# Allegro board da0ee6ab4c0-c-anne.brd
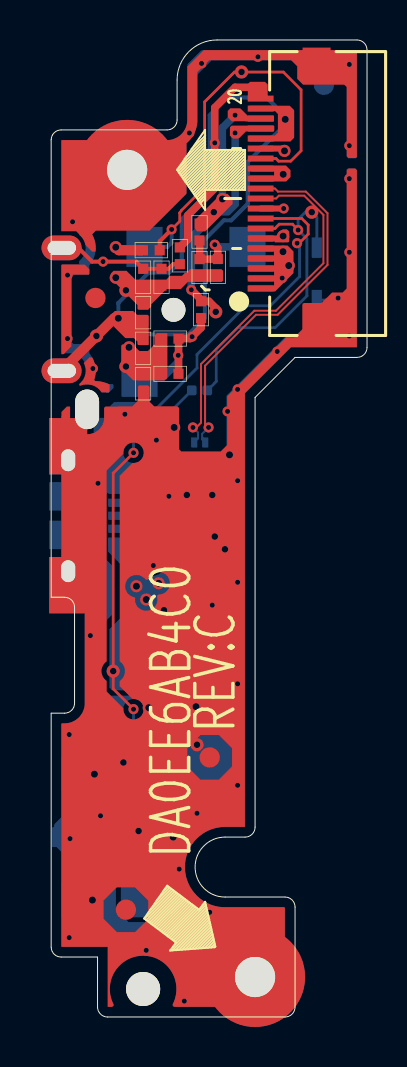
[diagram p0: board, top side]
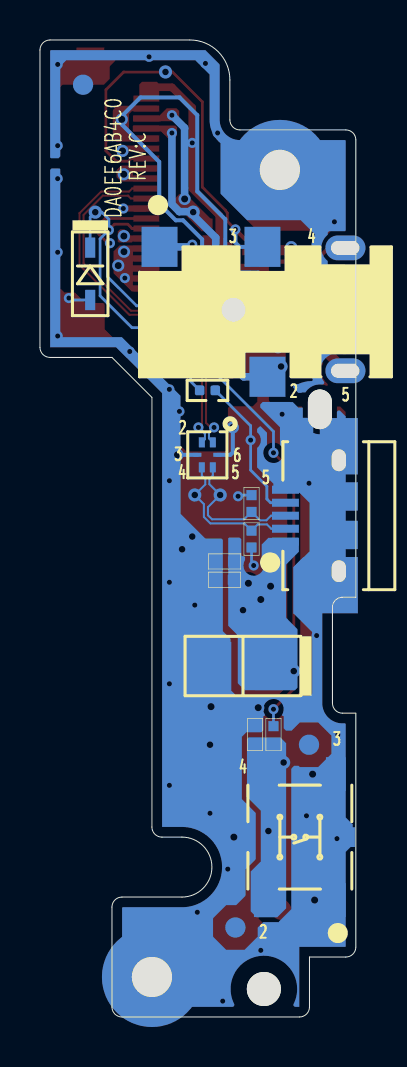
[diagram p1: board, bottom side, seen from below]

Outline 15.8 x 48.88 mm; copper layers: TOP, SGND, SVCC, BOTTOM. Coordinates in mm from the lower left corner of the outline.
Outline path: 0,43.88 arc(0.15,44.24) 0.5,44.38 5.8,44.38 arc(6.15,44.53) 6.3,44.88 6.3,46.88 arc(6.89,48.3) 8.3,48.88 15.3,48.88 arc(15.65,48.74) 15.8,48.38 15.8,33.5 arc(15.65,33.15) 15.3,33 12.2,33 10.2,31 10.2,9.5 arc(10.05,9.15) 9.7,9 8.7,9 arc(7.2,7.5) 8.7,6 11.7,6 arc(12.05,5.85) 12.2,5.5 12.2,0.5 arc(12.05,0.15) 11.7,0 2.82,0 arc(2.47,0.15) 2.32,0.5 2.32,3 0.5,3 arc(0.15,3.15) 0,3.5 0,15.2 0.67,15.2 arc(1.02,15.35) 1.17,15.7 1.17,20.5 arc(1.02,20.85) 0.67,21 0,21 0,32.01 0.89,32.01 arc(1.22,32.33) 0.89,32.66 0,32.66 0,38.15 0.89,38.15 arc(1.22,38.48) 0.89,38.8 0,38.8 0,43.88

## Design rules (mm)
constraint set DEFAULT: min track width 0.14
net group DFP-S4W4-TB: nets USB_FS_DM_R USB_FS_DP_R USBP4+_CN USBP4-_CN
net group W15-TB: nets HEADSET_MIC HP_OUT_L HP_OUT_L_CON HP_OUT_R HP_OUT_R_CON
net group W80-TB: nets DCIN_5V_IN

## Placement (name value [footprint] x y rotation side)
C1  330p/50v_4  [CC0402_S]  8.34 37.5 270 top
C2  330p/50v_4  [CC0402_S]  5.95 32.18 180 top
C3  330p/50v_4  [CC0402_S]  4.6 37.01 270 top
C4  470p/50v_4  [CC0402_S]  6.56 22.79 180 bottom
C5  0.1u/10v_4  [CC0402_S]  6.57 21.87 180 bottom
C6  150u/6.3v_3528  [CC3528]  5.64 17.56 180 bottom
CN1  88511-2001-20p-l  [88511-2001-20P-L]  13.78 41.2 90 top
CN2  2sj2342-000111f  [PHJK-2SJ2342-000111F-5P]  4.52 35.38 270 bottom
CN3  micro_usb2.0  [USB-2UB1000-000201F-5P-L]  0.85 25.08 90 bottom
D1  *5v/0.2p_4  [CC0402_S]  5.22 23.91 270 bottom
D2  *5v/0.2p_4  [CC0402_S]  5.22 25.69 90 bottom
D6  udzvte-173.3b  [DSM]  13.29 37.19 270 bottom
HOLE1  *h-c197d79p2  [H-C197D79P2]  10.2 2 0 top
HOLE2  *h-c197d79p2  [H-C197D79P2]  3.8 42.38 0 top
HOLE3  *h-c67d67n  [H-C67D67N]  4.6 1.4 0 top
HOLE4  *h-o47x78d47x78n  [H-O47X78D47X78N]  1.8 30.4 0 top
L3  33_4  [RC0402_S]  7.5 35.39 270 top
L4  33_4  [RC0402_S]  7.42 39.28 270 top
NOREF  -  []  7.43 -22.93 0 top
NOREF#2  -  [unnamed#2]  2.21 35.97 0 top
NOREF#3  -  []  -42.86 -64.59 0 top
NOREF#4  -  [unnamed#2]  7.93 12.99 0 top
NOREF#5  -  [unnamed#2]  3.74 5.37 0 top
NOREF#6  -  [unnamed#2]  6.02 4.48 180 bottom
NOREF#7  -  [unnamed#2]  13.64 46.64 180 bottom
NOREF#8  -  [unnamed#2]  2.34 13.62 180 bottom
R1  0_4  [RC0402_S]  6.44 38.08 270 top
R4  0_4  [RC0402_S]  4.6 33.46 90 top
R5  0_4  [RC0402_S]  4.6 31.68 90 top
R99  100/f_4  [RC0402]  7.42 31.35 180 bottom
R327  0_4  [RC0402_S]  4.12 14.13 270 bottom
SW1  tme-532w-q-t/r(439)  [SW-TC901-AA1G-A160T-6P]  2.8 9 0 bottom
T1  rclamp0531t  [RC0402_S]  7.42 37.5 90 top
T2  rclamp0531t  [RC0402_S]  5.95 33.94 0 top
T3  rclamp0531t  [RC0402_S]  5.52 37.01 90 top
T4  rclamp0531t  [RC0402_S]  4.6 35.23 270 top
T5  rclamp0531t  [RC0402_S]  5.01 38.36 0 top
T6  0.2pf/12v_4  [RC0402_S]  5.04 14.13 90 bottom
U3025  lxes11daa2-135  [FILTER-LXES11DAA2-135-6P]  7.43 28.12 180 bottom

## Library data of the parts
C1-C5 D1 D2 = CC0402_S
C6 = CC3528
CN1 = 88511-2001-20P-L
CN2 = PHJK-2SJ2342-000111F-5P
CN3 = USB-2UB1000-000201F-5P-L
D6 = DSM
HOLE1 HOLE2 = H-C197D79P2
HOLE3 = H-C67D67N
HOLE4 = H-O47X78D47X78N
L3 L4 R1 R4 R5 R327 T1-T6 = RC0402_S
R99 = RC0402
SW1 = SW-TC901-AA1G-A160T-6P
U3025 = FILTER-LXES11DAA2-135-6P

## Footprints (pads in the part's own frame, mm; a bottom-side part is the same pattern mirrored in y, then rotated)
88511-2001-20P-L
  rect 0.305x1.295 smd: 1(-4.75,3.3) 2(-4.25,3.3) 3(-3.75,3.3) 4(-3.25,3.3) 5(-2.75,3.3) 6(-2.25,3.3) 7(-1.75,3.3) 8(-1.25,3.3) 9(-0.75,3.3) 10(-0.25,3.3) 11(0.25,3.3) 12(0.75,3.3) 13(1.25,3.3) 14(1.75,3.3) 15(2.25,3.3) 16(2.75,3.3) 17(3.25,3.3) 18(3.75,3.3) 19(4.25,3.3) 20(4.75,3.3)
  rect 1.803x1.397 smd: 21(-6.4,0.5) 22(6.4,0.5)
CC0402_S
  rect 0.508x0.508 smd: 1(-0.42,0) 2(0.42,0)
CC3528
  rect 2.032x2.413 smd: 1(1.6,0) 2(-1.6,0)
DSM
  rect 1.016x0.508 smd: 1(-1.3,0) 2(1.321,0)
FILTER-LXES11DAA2-135-6P
  rect 0.305x0.508 smd: 1(0.275,0.625) 2(-0.275,0.625) 4(-0.275,-0.625) 5(0.275,-0.625)
  rect 0.406x0.203 smd: 3(-0.5,0) 6(0.5,0)
H-C67D67N
  round 1.702 hole 1.702 unplated: (0,0)
H-C197D79P2
  round 5.004 hole 2.007: 1(0,0)
H-O47X78D47X78N
  oval 1.194x1.981 hole 1.194x1.981 unplated: (0,0)
PHJK-2SJ2342-000111F-5P
  round 1.194 hole 1.194 unplated: (0,-1.6)
  rect 2.007x1.803 smd: 1(-3.15,-5.3) 2(3.35,0.1) 3(-3.15,-0.15)
  oval 1.245x2.007 hole 0.66x1.397: 4(-3.1,4) 5(3.05,4)
RC0402
  custom 0.12x0.12 smd: 1(0.39,0) 2(-0.39,0)
RC0402_S
  rect 0.508x0.508 smd: 1(-0.42,0) 2(0.42,0)
SW-TC901-AA1G-A160T-6P
  rect 0.991x1.702 smd: 1(-1.8,3.15) 2(1.8,3.15) 3(-1.8,-3.15) 4(1.8,-3.15)
  rect 0.457x0.991 smd: 5(-2.525,0) 6(2.525,0)
unnamed#2
  round 1.016 smd: 1(0,0)
USB-2UB1000-000201F-5P-L
  rect 0.406x1.346 smd: 1(-1.3,2.67) 2(-0.65,2.67) 3(0,2.67) 4(0.65,2.67) 5(1.3,2.67)
  rect 2.819x1.905 hole 1.092x0.711: 6(-2.775,0) 7(2.775,0)
  custom 0.25x0.25 smd: 8(-3.487,1.78) 9(3.487,1.78)
  rect 1.422x1.905 smd: 10(-0.962,0) 11(0.962,0)

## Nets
AGND: C1.2 C2.2 C3.2 CN1.15 CN1.22 HOLE2.1 R4.1 R5.2 T1.1 T2.1 T3.1 T4.1 T5.1
GND: C4.1 C5.1 C6.2 CN1.6 CN1.9 CN1.12 CN1.13 CN1.21 CN3.5 CN3.6 CN3.7 CN3.8 CN3.9 CN3.10 CN3.11 D1.2 D2.2 D6.2 HOLE1.1 R5.1 SW1.1 SW1.3 SW1.5 SW1.6 T6.2 U3025.3 U3025.6
COM_MIC_JACK: C3.1 CN2.4 R1.2 T3.2
DCIN_5V_IN: C4.2 C5.2 C6.1 CN1.1 CN1.2 CN1.3 CN1.4 CN1.5 CN3.1
HEADSET_MIC: CN1.20 R1.1
HOME_SCREEN: CN1.8 R327.1
HP_AGND: CN1.16 CN1.19 CN2.5 R4.2 T4.2
HP_DET: CN1.14 CN2.3 T5.2
HP_OUT_L: CN1.18 L4.1
HP_OUT_L_CON: C1.1 CN2.1 L4.2 T1.2
HP_OUT_R: CN1.17 L3.1
HP_OUT_R_CON: C2.1 CN2.2 L3.2 T2.2
USB_DCIN_IDN: CN1.7 D6.1 R99.2
USB_DCIN_IDN_C: CN3.4 R99.1
USB_FS_DM_R: CN1.11 U3025.2
USB_FS_DP_R: CN1.10 U3025.1
USBP4+_CN: CN3.3 D2.1 U3025.5
USBP4-_CN: CN3.2 D1.1 U3025.4
N38170283: R327.2 SW1.2 SW1.4 T6.1

Pads without a net: NOREF#2 1; NOREF#4 1; NOREF#5 1; NOREF#6 1; NOREF#7 1; NOREF#8 1

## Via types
v1: diameter 0.508, hole 0.254, TOP to BOTTOM, 53 vias
v2: diameter 0.66, hole 0.33, TOP to BOTTOM, 16 vias
v3: diameter 0.61, hole 0.356, TOP to BOTTOM, 21 vias

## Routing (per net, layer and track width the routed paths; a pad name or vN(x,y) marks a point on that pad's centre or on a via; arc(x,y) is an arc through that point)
AGND: length 2.7
  TOP w0.305: v3(11.67,43.33) 11.55,43.45 CN1.15
  TOP w0.508: T5.1 3.38,38.36 v3(3.23,38.51)
  vias: v1(0.82,37.12) v1(0.82,33.94) v1(1.07,39.78) v1(2.09,32.44) v1(6.91,44.23) v1(7.52,47.71) v1(10.34,48.04) v1(14.91,47.66) v1(14.91,43.59) v2(3.74,36.36) v2(3.74,32.55) v3(3.23,36.99) v3(3.89,33.5)
GND: length 9.8
  TOP w0.305: v1(11.63,40.45) 11.63,40.45 CN1.9
  BOTTOM w0.14: v1(5.89,26.05) 5.83,26.11 D2.2 ; v1(14.35,35.97) 14.26,35.87 D6.2 ; v1(5.11,22.59) 5.22,22.69 D1.2
  BOTTOM w0.203: v3(6.15,29.5) 6.15,28.25 6.28,28.12 U3025.6 ; v3(8.92,28.12) U3025.3
  BOTTOM w0.508: SW1.6 v3(6.1,9) ; C6.2 v3(7.24,15.53)
  vias: v1(0.9,14.13) v1(0.94,8.92) v1(0.9,3.97) v1(1.96,19.08) v1(2.34,26.7) v1(2.47,10.07) v1(3.69,30.16) v1(4.75,3.34) v1(6.41,7.4) v1(6.66,0.8) v1(7.29,10.19) v1(7.93,5.24) v1(8.06,20.61) v1(8.82,30.3) v1(9.33,31.4) v1(9.33,26.83) v1(9.33,21.75) v1(9.33,16.67) v1(9.33,11.59) v1(11.31,33.3) v1(14.91,41.94) v1(14.91,38.26) v1(14.91,34.07) v2(4.37,9.3) v2(7.29,13.62) v2(8.18,24.04) v2(8.69,23.4) v3(2.06,5.85) v3(2.16,12.15) v3(4.88,15.48) v3(11.61,42.16) v3(11.6,39.07)
COM_MIC_JACK: length 6.4
  TOP w0.203: R1.2 6.11,37.66 5.87,37.43 T3.2 C3.1 4.24,37.79 v1(2.6,37.79) 2.05,37.79 1.36,38.48 CN2.4
DCIN_5V_IN:
  vias: v1(11.55,36.97) v2(5.64,20.35) v3(4.26,21.55) v3(4.75,20.89) v3(5.37,21.7) v3(11.6,38.29) v3(11.88,37.59)
HEADSET_MIC: length 10
  TOP w0.381: 10.06,46.52 9.2,46.52 8.18,45.5 v1(8.18,43.73) 8.18,41.46 6.83,40.11 6.83,38.9 R1.1
HOME_SCREEN: length 32.9
  TOP w0.14: v1(4.12,28.23) 3.1,27.21 v2(3.1,17.31) 3.1,16.42 v1(4.12,15.4) ; v1(12.3,38.71) 12.4,38.71 12.86,39.17 12.86,39.63 12.54,39.95 CN1.8
  BOTTOM w0.14: R327.1 v1(4.12,15.4) ; v1(4.12,28.23) 4.12,29.29 7.29,32.47 7.29,33.14 9.73,35.58 10.96,35.58 12.43,37.04 12.43,38.59 v1(12.3,38.71)
HP_AGND: length 38.1
  TOP w0.508: v3(3.36,34.96) 3.15,34.96 v2(2.26,34.07) CN2.5
  BOTTOM w0.203: 11.68,44.91 11.68,45.1 10.77,46.01 8.82,46.01 7.93,45.12 7.93,41.31 6.53,39.91 6.53,37.88 5.9,37.24 4.88,37.24 3.36,35.72 v3(3.36,34.96) 4.16,34.15 6.87,34.15 7.69,34.97 7.69,38.91 8.64,39.86 9.01,39.86 9.83,40.69 9.83,42.78 11.68,44.63 11.68,44.91 ; 11.68,44.91 v3(11.71,44.91)
HP_DET: length 21.6
  TOP w0.14: CN1.14 10.89,42.95 11.25,42.95 11.38,42.82 11.98,42.82 12.5,43.34 12.5,46.39 11.61,47.28 9.53,47.28 v2(9.52,47.28) 9.52,47.28 9.17,47.28 7.68,45.79 7.68,41.52 6.52,40.36 6.43,40.23 6.43,40.22 6.43,39.81 v1(6.02,39.4)
  TOP w0.203: T5.2 5.43,38.81 v1(6.02,39.4)
  BOTTOM w0.203: CN2.3 5.81,38.53 6.02,38.74 v1(6.02,39.4)
HP_OUT_L: length 4.5
  BOTTOM w0.381: v1(9.2,45.12) 8.56,44.48 v3(8.56,40.93)
  vias: v2(8.13,40.27)
HP_OUT_L_CON: length 4.3
  TOP w0.381: L4.2 T1.2 8.33,37.92 C1.1 8.34,38.49 v1(8.18,38.64)
  BOTTOM w0.381: v1(8.18,38.64) 8.29,38.53 CN2.1
HP_OUT_R: length 10.9
  TOP w0.381: v1(7.01,36.38) 7.01,36.38 7.5,35.9 L3.1 7.89,35.81 8.23,35.47 v2(8.23,35.28)
  BOTTOM w0.381: v1(7.01,36.38) 7.01,38.99 8.31,40.29 8.83,40.29 9.2,40.66 v1(9.2,44.23)
HP_OUT_R_CON: length 6.2
  TOP w0.381: C2.1 6.37,33.09 v1(6.36,33.1) 6.37,33.12 T2.2 6.95,33.94 v1(7.05,34.04) 7.05,34.04 7.5,34.48 L3.2
  BOTTOM w0.381: v1(6.36,33.1) 6.36,32.77 5.61,32.03 CN2.2
USB_DCIN_IDN: length 16.7
  TOP w0.14: v1(12.35,39.37) 12.35,39.38 12.07,39.66 11.41,39.66 11.19,39.45 CN1.7
  BOTTOM w0.14: D6.1 13.29,40.01 v2(13.04,40.27) 12.71,40.27 12.35,39.91 v1(12.35,39.37) 12.79,38.93 12.79,36.08 11.2,34.49 9.34,34.49 8.26,33.41 8.26,31.8 R99.2
USB_DCIN_IDN_C: length 7.5
  BOTTOM w0.14: R99.1 5.26,29.58 v1(5.26,28.86) 5.26,27.36 4.45,26.55 4.45,25.92 4.26,25.73 CN3.4
USB_FS_DM_R: length 18.8
  TOP w0.102: v1(7.87,29.5) 7.7,29.67 7.7,32.58 10.25,35.13 11.33,35.13 13.82,37.63 13.82,40.21 12.74,41.3 11.35,41.3 11.19,41.45 10.48,41.45 CN1.11
  BOTTOM w0.102: U3025.2 7.55,28.9 7.55,29.17 v1(7.87,29.5)
USB_FS_DP_R: length 18.6
  TOP w0.102: v1(7.09,29.5) 7.26,29.5 7.49,29.73 7.49,32.67 10.16,35.33 11.24,35.33 13.62,37.71 13.62,40.13 12.66,41.09 11.39,41.09 11.25,40.95 CN1.10
  BOTTOM w0.102: U3025.1 7.35,28.94 7.35,29.24 v1(7.09,29.5)
USBP4+_CN: length 7.3
  BOTTOM w0.102: CN3.3 4.24,25.08 4.48,24.85 4.8,24.85 D2.1 5.59,24.9 7.19,24.9 7.4,25.1 7.4,25.51 v2(6.79,26.12) 7.33,26.66 7.33,26.91 7.15,27.09 U3025.5
USBP4-_CN: length 7.5
  BOTTOM w0.102: CN3.2 4.23,24.43 4.45,24.65 4.9,24.65 D1.1 5.58,24.7 7.28,24.7 7.6,25.02 7.6,25.66 v2(8.06,26.12) 7.53,26.64 7.53,26.91 7.7,27.09 U3025.4
N38170283:
  vias: v2(3.61,12.73)

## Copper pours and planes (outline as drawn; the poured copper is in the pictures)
AGND on TOP (solid shape): 1.91,37.41 1.91,37.19 1.9,37.15 1.86,37.14 1.02,37.14 1.02,33.54 0.63,33.16 0.51,33.16 0.51,37.62 0.54,37.65 1.67,37.65
AGND on TOP (solid shape): 5.81,34.18 5.81,32 5.66,31.85 4.1,31.85 3.5,32.45 3.5,33.59 3.56,33.65 4.08,33.65 4.41,33.32 4.84,33.32 5.17,33.65 5.17,34.09 5.29,34.2 5.79,34.2
AGND on TOP (solid shape): 8.6,37.34 8.6,36.84 8.53,36.78 6.84,36.78 6.49,36.42 5.77,36.42 5.01,35.66 5.01,35.55 4.85,35.39 4.36,35.39 4.32,35.44 4.32,35.62 3.01,36.92 3.01,37.22 3.12,37.33 3.77,37.33 4.21,36.89 5.75,36.89 5.95,37.08 6.54,37.08 6.69,37.24 6.76,37.24 6.94,37.41 8.52,37.41
AGND on TOP (solid shape): 2.05,33 2.22,32.45 2.15,31.88 2.15,31.87 2.2,31.82 2.54,31.78 2.87,31.67 2.88,31.66 2.9,31.66 2.92,31.64 2.92,31.3 2.88,31.25 2.52,31.25 2.05,31.61 1.47,31.58 1.43,31.58 1.4,31.61 1.4,31.65 1.42,31.69 1.43,31.7 1.71,32.17 1.63,32.72 1.91,33
AGND on TOP (solid shape): 15.29,43.04 15.23,42.97 14.87,42.97 14.78,43.06 14.78,46.52 14.66,46.64 12.61,46.64 12.31,46.94 12.31,47.56 12,47.87 7.9,47.87 7.32,47.28 7.32,44.88 7.17,44.24 6.77,43.71 6.77,41.19 4.92,39.34 2.23,39.34 2.05,39.16 2.21,38.74 2.22,38.29 2.05,38.29 1.71,38.64 1.61,38.9 1.43,39.11 1.42,39.12 1.4,39.16 1.25,39.31 0.51,39.31 0.51,43.84 0.54,43.87 5.8,43.87 6.51,44.17 6.81,44.88 6.81,47.55 7.63,48.37 15.29,48.37
AGND on BOTTOM (solid shape): 15.29,48.34 15.29,43.01 15.25,42.96 14.88,42.96 14.78,43.06 14.78,47.56 14.48,47.87 8.03,47.87 7.32,47.15 7.32,44.88 7.17,44.24 6.77,43.71 6.77,41.19 5.44,39.86 2.76,39.86 2.05,39.16 2.23,38.36 1.91,37.61 1.91,37.19 1.9,37.15 1.86,37.14 1.15,37.14 1.02,37.01 1.02,33.78 1.12,33.67 1.86,33.67 1.9,33.66 1.91,33.62 1.91,33.2 2.21,32.57 2.15,31.88 2.15,31.87 2.2,31.82 2.54,31.78 2.87,31.67 2.88,31.66 3.08,31.66 3.13,31.61 3.13,31.48 2.88,31.22 2.72,31.22 2.7,31.25 2.52,31.25 2.16,31.56 1.7,31.64 1.59,31.69 1.6,31.8 1.76,32.52 1.31,33.11 1.3,33.11 1.25,33.16 1.18,33.16 1.04,33.2 0.9,33.21 0.57,33.21 0.51,33.27 0.51,37.62 0.54,37.65 1.4,37.65 1.4,37.8 1.42,37.84 1.43,37.85 1.72,38.48 1.43,39.11 1.42,39.12 1.4,39.16 1.4,39.25 1.34,39.31 0.55,39.31 0.51,39.35 0.51,43.84 0.54,43.87 5.8,43.87 6.51,44.17 6.81,44.88 6.81,47.66 7.52,48.37 15.26,48.37
AGND on SGND (solid shape): outline of 176 points within 0.51,31.05 15.29,48.37
AGND on SVCC (solid shape): 14.78,43.41 14.33,42.96 11,42.96 10.09,42.05 10.09,38.6 9.77,38.29 9.77,38.26 9.42,37.9 8.67,37.9 6.82,36.05 5.15,35.48 6.67,34.58 6.67,33.09 6.48,32.9 4.57,32.9 2.74,31.07 2.5,31.48 2.1,31.73 2.07,32.98 1.02,33.67 1.02,37.14 2.24,38.48 1.02,39.82 1.02,43.37 5.8,43.37 6.87,43.81 7.32,44.88 7.32,46.88 7.6,47.58 8.3,47.87 14.78,47.87
GND on TOP (solid shape): 11.91,39.29 11.91,38.81 11.86,38.75 11.2,38.75 11.16,38.8 9.89,38.8 9.83,38.86 9.83,39.05 9.89,39.1 11.27,39.1 11.58,39.41 11.79,39.41
GND on TOP (solid shape): 11.97,42.37 11.97,42.02 11.75,41.8 9.99,41.8 9.93,41.86 9.93,42.06 9.96,42.1 11.13,42.1 11.15,42.11 11.15,42.28 11.13,42.3 10.01,42.3 9.93,42.39 9.93,42.56 9.96,42.6 11.74,42.6
GND on TOP (solid shape): outline of 511 points within 0.51,0.51 15.29,42.45
GND on BOTTOM (solid shape): outline of 405 points within 0.15,0.51 15.29,42.45
GND on SGND (solid shape): 15.29,42.06 15.29,33.51 12.65,33.51 12.65,33.51 11.99,33.51 9.81,31.33 9.69,31.33 9.69,9.51 8.7,9.51 6.69,7.5 8.7,5.49 11.69,5.49 11.69,0.51 6.18,0.51 6.09,0.56 6.09,0.66 4.6,3.06 3.11,0.66 3.11,0.56 3.02,0.51 2.83,0.51 2.83,3.51 0.51,3.51 0.51,14.69 0.67,14.69 1.38,14.99 1.68,15.7 1.68,20.5 1.38,21.21 0.67,21.51 0.51,21.51 0.51,29.09 1.44,29.09 2.35,29.19 2.78,30 2.78,30.55 5.22,30.55 7.09,32.41 7.09,33.33 8.39,34.62 8.39,36.07 10.6,38.28 10.6,41.84 11.21,42.45 14.9,42.45
GND on SVCC (solid shape): 14.78,41.88 14.78,34.02 13.13,34.02 12.7,34.45 12.7,38.42 11.77,39.35 11.19,39.35 10.6,39.95 10.6,39.98 10.6,41.84 11.21,42.45 14.22,42.45
GND on SVCC (solid shape): 9.18,29.48 9.18,10.02 8.7,10.02 6.18,7.5 8.7,4.98 11.18,4.98 11.18,1.02 6.22,1.02 5.35,2.88 3.34,2.48 3.34,4.02 1.02,4.02 1.02,14.22 1.86,14.76 2.19,15.7 2.19,19.15 2.59,19.55 5.9,19.55 6.79,20.44 6.79,23.63 6.26,24.16 3.84,24.16 3.61,24.4 3.61,25.84 3.97,26.2 5.75,26.2 6.84,27.28 6.84,29.7 6.99,29.85 8.82,29.85
DCIN_5V_IN on TOP (solid shape): 11.82,38.6 12.12,38.3 12.12,37.21 11.21,36.3 9.86,36.3 9.84,36.32 9.84,36.55 9.89,36.6 11.13,36.6 11.15,36.62 11.15,36.79 11.14,36.8 9.91,36.8 9.84,36.87 9.84,37.05 9.89,37.1 11.14,37.1 11.15,37.12 11.15,37.28 11.13,37.3 9.91,37.3 9.84,37.37 9.84,37.55 9.88,37.6 11.13,37.6 11.15,37.62 11.15,37.79 11.14,37.8 9.88,37.8 9.84,37.84 9.84,38.06 9.88,38.1 11.13,38.1 11.14,38.11 11.14,38.29 11.13,38.3 9.84,38.3 9.83,38.31 9.83,38.58 9.85,38.6 10.76,38.6
DCIN_5V_IN on BOTTOM (solid shape): 6.39,23.94 6.39,19.57 5.91,19.09 5.91,16.7 5.56,16.35 3.04,16.35 2.92,16.48 2.92,19.4 3.48,19.97 3.48,22.64 2.85,23.27 2.85,23.92 2.9,23.97 4.38,23.97 4.71,23.64 4.71,22.9 5.08,22.08 5.55,22.85 5.54,22.86 5.54,23.01 5.59,23.06 5.68,23.06 5.73,23.1 5.73,23.91 5.8,23.98 6.34,23.98
DCIN_5V_IN on SVCC (solid shape): 12.2,38.21 12.2,34.46 11.5,33.77 11.5,33.74 9.18,31.42 9.18,30.78 8.82,30.41 8.76,30.41 8.71,30.36 6.78,30.36 6.33,29.91 6.33,27.49 5.54,26.7 3.76,26.7 3.1,26.05 3.1,24.18 3.63,23.66 6.05,23.66 6.28,23.42 6.28,20.65 5.69,20.06 2.47,20.06 2.19,20.34 2.19,20.5 1.86,21.44 1.02,21.98 1.02,29.42 2.11,29.07 2.78,30 2.78,30.49 2.88,30.49 4.78,32.39 6.69,32.39 7.17,32.88 7.17,35.69 8.88,37.4 9.63,37.4 11.06,38.82 11.22,38.82 11.24,38.85 11.56,38.85
HP_AGND on TOP (solid shape): 4.3,35.13 4.83,35.13 4.88,35.08 4.88,33.64 4.85,33.62 4.36,33.62 4.31,33.66 4.31,33.79 4.14,33.97 3.71,33.97 3.45,34.23 2.94,34.74 2.94,35.08 3.18,35.32 4.11,35.32
HP_AGND on TOP (solid shape): 12.15,45.37 12.15,43.99 11.97,43.8 9.92,43.8 9.87,43.85 9.87,44.08 9.89,44.1 11.19,44.1 11.34,44.25 11.34,45.18 11.2,45.32 9.91,45.32 9.86,45.37 9.86,45.52 9.93,45.59 11.93,45.59
HP_OUT_L on TOP (solid shape): 9.07,40.93 9.07,40.67 7.71,39.31 7.3,39.31 7.22,39.39 7.22,39.9 8.5,41.18 8.82,41.18
HP_OUT_L on TOP (solid shape): 9.83,45.1 11.13,45.1 11.14,45.09 11.14,44.82 11.13,44.81 9.74,44.81 9.73,44.81 9.03,44.81 8.83,45.01 8.83,45.33 8.96,45.46 9.46,45.46
HP_OUT_R on TOP (solid shape): 11.16,44.57 11.16,44.34 11.12,44.3 9.74,44.3 9.39,43.95 9.09,43.95 8.94,44.09 8.94,44.51 9.03,44.6 11.13,44.6
N38170283 on BOTTOM (solid shape): 5.45,13.91 5.45,11.01 4.75,10.32 4.75,7.78 5.26,7.27 5.26,5.29 4.96,4.99 3.93,4.99 3.48,5.43 3.48,13.7 3.77,13.99 5.37,13.99

Small or netless copper shapes (teardrops, artwork), in the pictures only: 2 on TOP

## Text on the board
Ref Des/Silkscreen Bottom: REV:C | DA0EE6AB4C0
User.Comments: 47.0x78.0
Ref Des/Silkscreen Top: DA0EE6AB4C0 | REV:C
User.45: FIGURE | TYPE | Circle | Oblong | SIZE | 10.0 | 14.0 | 79.0 | 47.0 | 67.0 | 43.0x28.0 | 55.0x26.0 | DRILL CHART: TOP to BOTTOM | ALL UNITS ARE IN MILS | PLATED | NON-PLATED | ROTATION | - | 0.000 | 90.000 | QTY | 49 | 21 | 2 | 1 | 74 | 5 | TOTAL HOLES:
